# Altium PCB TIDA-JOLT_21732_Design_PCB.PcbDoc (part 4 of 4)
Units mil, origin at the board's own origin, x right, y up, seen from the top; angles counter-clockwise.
Board outline 5511.81 x 3149.61 mil, 4 copper layers (Top Layer, Power, Ground, Bottom Layer), stack 104.204 mil thick; 440 components, 201 nets, 1044 pads, 391 vias.
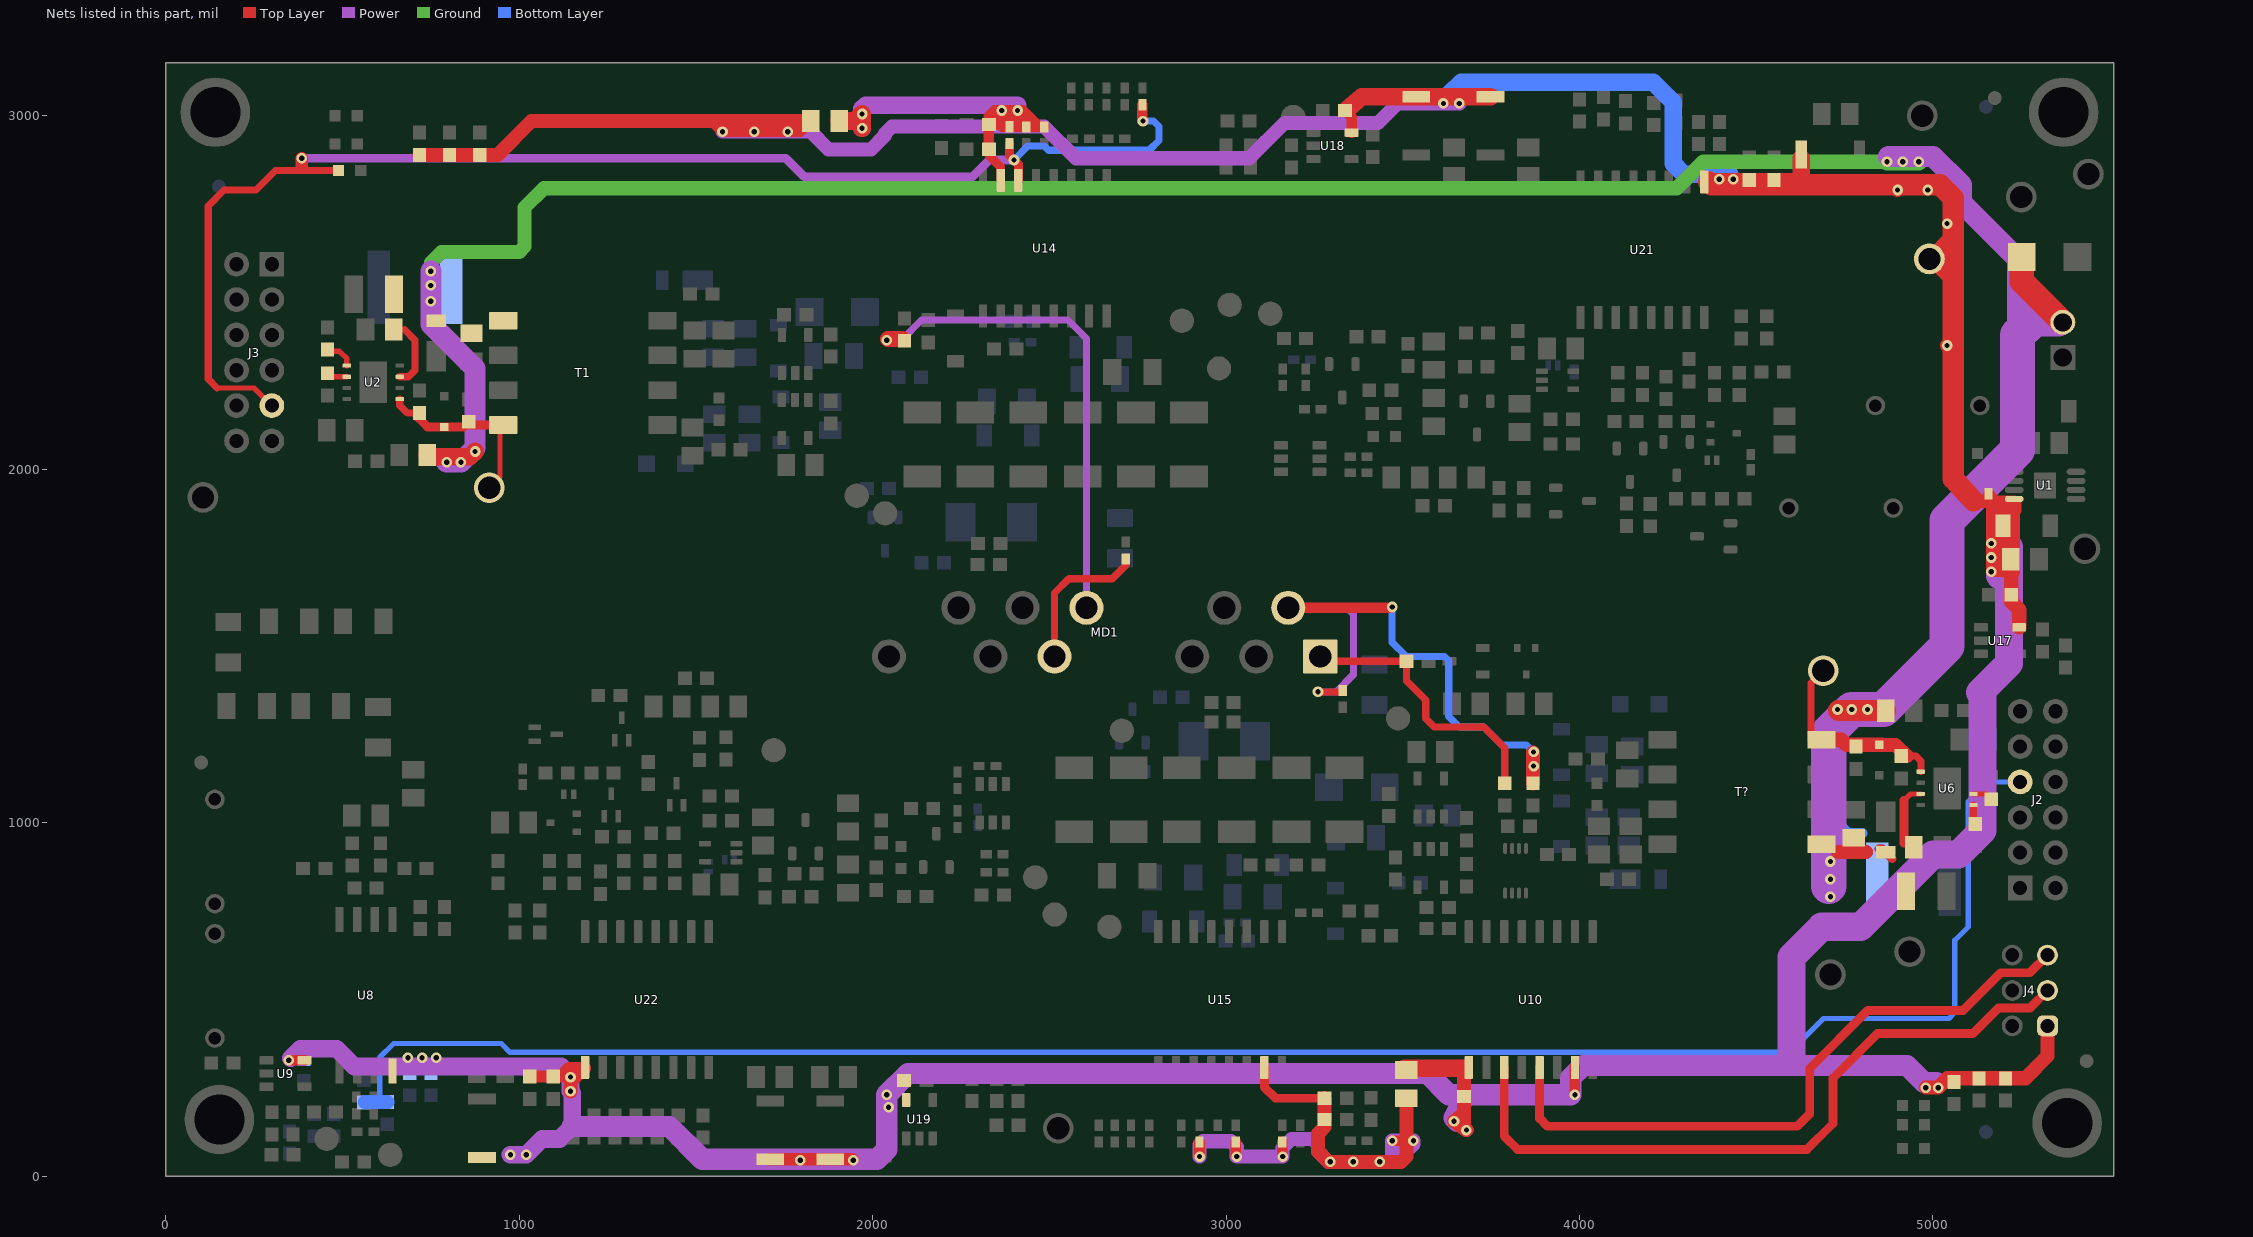
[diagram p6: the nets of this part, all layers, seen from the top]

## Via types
v1: diameter 30, hole 15, Top Layer to Bottom Layer, 378 vias
v2: diameter 19.68, hole 7.87, Top Layer to Bottom Layer, 13 vias

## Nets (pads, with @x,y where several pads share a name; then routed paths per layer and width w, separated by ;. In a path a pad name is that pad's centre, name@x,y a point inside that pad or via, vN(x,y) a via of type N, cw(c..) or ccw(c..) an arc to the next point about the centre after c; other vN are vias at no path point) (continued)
RST/EN_U: C85.1 D22.1 J3.9 R61.1 U14.14 | length 3881
  Top Layer w15: 145,2230 250,2230 J3.9@300,2180
  Top Layer w20: 145,2230 120,2255 120,2745 165,2790 255,2790 310,2845 D22.1@488.5,2845
  Top Layer w25: R61.1@2387.18,2921.73 2387.18,2887.82 v1(2400,2875) 2412.18,2862.82 U14.14@2412.18,2817.28
  Top Layer w30: v1@2763.31,2986.69 C85.1@2763.31,3031.1
  Top Layer w35: 385,2860 v1(385,2880)
  Power w25: v1(385,2880) 1754.11,2880 1806.56,2827.55 2282.55,2827.55 2330,2875 v1(2400,2875)
  Bottom Layer w20: v1(2400,2875) 2440,2915 2485,2915 2497.55,2902.45 2782.45,2902.45 2810,2930 2810,2970 2795,2985 v1(2765,2985)
SCLK_temp_L: J4.3 U10.3 | length 2009.2
  Top Layer w25: U10.3@3787.05,307.44 3787.05,112.95 3825,75 4643.51,75 4717.13,148.62 4717.13,277.13 4842.87,402.87 5112.87,402.87 5185,475 5274.37,475 J4.3@5324.33,524.96
SDO_temp_L: J4.5 U10.5 | length 1866.8
  Top Layer w25: U10.5@3887.05,307.44 3887.05,162.95 3909.25,140.75 4616.28,140.75 4651.38,175.85 4651.38,304.36 4815.64,468.62 5085.64,468.62 5192.02,575 5274.37,575 J4.5@5324.33,624.96
SS_L: C38.1 U6.5 | length 55.3
  Top Layer w20: U6.5@5114.93,1049.6 5114.93,1001.44 C38.1@5120,996.37
SS_U: C17.1 U2.5 | length 83.5
  Top Layer w15: C17.1@457.1,2333.5 491.5,2333.5 512.29,2312.71 U2.5@512.29,2293
SW_L: C26.2 D14.2 R17.2 T?.4 TP3.1 U6.1 | length 595
  Top Layer w20: T?.4@4655,1233.8 4655,1395 TP3.1@4690,1430 ; R17.2@4911.1,1188.35 4951.65,1188.35 4966.3,1173.7 U6.1@4966.3,1144.09
  Top Layer w40: T?.4@4685,1234.44 4740.56,1234.44 4754.84,1220.16 D14.2@4856.1,1220.16 ; 4822.76,1220 4894.45,1220 R17.2@4926.1,1188.35
SW_U: C6.2 D5.2 R6.2 T1.4 TP1.1 U2.1 | length 523.4
  Top Layer w15: TP1.1@915,1947.4 945.4,1977.8 T1.4@945.4,2125.56
  Top Layer w20: U2.1@661.9,2198.52 661.9,2179.84 683.24,2158.5 R6.2@715,2158.5
  Top Layer w25: R6.2@715,2158.5 715,2145 740.7,2119.3 D5.2@788.2,2119.3 842.13,2119.3 C6.2@857.1,2134.26 ; C6.2@855.39,2125 T1.4@935,2125
T_L+: MD1.4 R43.1 R171.1 | length 791.7
  Top Layer w20: MD1.4@3266.38,1470 3279.8,1456.58 R171.1@3510.08,1456.58 3510.08,1401.38 3565,1346.46 3565,1295 3590,1270 3730,1270 3788.5,1211.5 R43.1@3788.5,1111.5
T_L-: MD1.5 R44.1 R82.2 | length 1714.9
  Top Layer w20: v1(3260,1370) 3326.38,1370 R82.2@3330,1373.62
  Top Layer w30: MD1.5@3190,1593.62 MD1.5@3175.83,1607.8 v1@3467.8,1607.8
  Top Layer w40: R44.1@3868.5,1111.5 v1@3868.5,1198.5
  Power w20: MD1.5@3175.83,1607.8 3342.2,1607.8 3360,1590 3360,1418.35 3311.65,1370 v1(3260,1370)
  Bottom Layer w20: v1(3470,1610) 3470,1510 3510,1470 3618.31,1470 3630,1458.31 3630,1300 3660,1270 3730,1270 3780,1220 3850,1220 v1(3870,1200) v1(3870,1160)
T_U+: MD1.9 R72.1 | length 1414.2
  Top Layer w45: v1@2043.5,2368.5 R72.1@2085,2368.5
  Power w20: v1(2040,2365) 2081.18,2365 2138.63,2422.45 2552.47,2422.45 2604.96,2369.96 MD1.9@2604.96,1607.8
T_U-: MD1.10 R78.2 | length 432
  Top Layer w20: MD1.10@2514.41,1470 2514.41,1649.41 2555,1690 2678,1690 2716.26,1728.26 R78.2@2716.26,1746.38
TC_L: R18.1 U6.6 | length 56.3
  Top Layer w15: U6.6@5114.93,1081.1 5150.08,1081.1 R18.1@5165,1066.18
TC_U: R7.1 U2.6 | length 57.3
  Top Layer w15: R7.1@457.1,2266.5 462.08,2261.51 U2.6@512.29,2261.51
V_DCBus: C49.1 J2.7 R36.1 | length 5504.7
  Bottom Layer w15: 598.15,209.53 605,216.38 605,335 645,375 949,375 974,350 4595,350 4690.76,445.76 5045,445.76 5061.85,462.6 5061.85,666.85 5100,705 5100,1059.96 5155,1114.96 J2.7@5246.77,1114.96
  Bottom Layer w40: R36.1@563.39,209.53 598.15,209.53 C49.1@626.69,209.53
VCC1: C4.1 C5.1 C43.1 C44.2 C46.2 C55.2 C100.1 C101.2 C102.2 C108.2 C112.1 C121.2 C125.1 J4.1 R4.2 R58.1 R75.1 R76.1 R77.1 R83.1 R102.1 R103.1 R104.1 S1.1 S2.1 S3.1 S4.1 S5.1 S6.1 TP18.1 U1.8 U8.8 U9.5 U10.1 U10.7 U17.5 U18.5 U19.5 U21.1 U22.1 | length 17364.6
  Top Layer w30: v1(347.4,327.4) U9.5@392.87,327.4 ; 1545,2985 v1(1575,2955) v1(1665,2955) v1(1760,2955) 1795,2955 R58.1@1825,2985 ; C101.2@3336.5,3025.55 C101.2@3336.5,3015 3355.23,2996.26 U18.5@3355.23,2952.4 ; v1@3987.05,235 U10.7@3987.05,307.44 ; R4.2@5157.4,1930.51 5177.88,1910.03 U1.8@5229.8,1910.03 ; 5165,1898.54 v1(5165,1790) v1(5165,1750) v1(5165,1710) 5190,1710 ; 5190,1897.91 5190,1710 ; 5221.18,1710 5190,1710
  Top Layer w35: C125.1@1030,281.5 C121.2@1096.3,281.5 ; 1116.3,281.5 1139.8,305 U22.1@1183,305 ; S4.1@1710,47.32 S6.1@1880,47.32 v1@1942.68,47.32
  Top Layer w40: R75.1@717.95,2889.33 R76.1@802.95,2889.33 R77.1@887.95,2889.33 939.33,2889.33 1035,2985 1545,2985 R58.1@1825,2985 ; v1(1145,240) 1145,267 U22.1@1183,305 ; 3675,305 3673.5,303.5 C55.2@3673.5,225 3673.5,180 ; v1(4900,2790) 4900,2805 ; v1(4980,250) v1(5015,250) 5041.5,276.5 R103.1@5130,276.5 R104.1@5205,276.5 5261.5,276.5 5324.33,339.33 J4.1@5324.33,424.96 ; v1(5040,2350) 5057.63,2350 ; 5040,2550 4995,2595 TP18.1@4990,2595 5057.63,2662.63 ; 5114.97,1910.03 5153.51,1910.03 ; 5220.47,1834.13 5220.47,1875.47 5221.5,1876.5 5230,1885 5230,1900 ; 5221.5,1709.68 C100.1@5221.5,1645 5221.5,1625 5244.13,1602.36 U17.5@5244.13,1552.4 ; 3673.5,180 3648.5,155 v1(3645,155) v1(3680,130) 3673.5,136.5 3673.5,180
  Top Layer w50: C101.2@3345,3020 3383.98,3053.98 ; 3388.98,3053.98 S3.1@3537.91,3053.98 S1.1@3747.91,3053.98 ; R83.1@3505,305.1 3510,305.1 3672.01,305 ; 4365,2813.23 4613.23,2813.23 4627.32,2827.32 S2.1@4627.32,2880 ; 5220.47,1875.47 5220.47,1890.47 ; 5221.5,1709.68 5221.5,1876.5 5221.5,1891.5
  Top Layer w60: 4365,2813.23 4373.23,2805 4900,2805 5020,2805 5057.63,2767.37 5057.63,2662.63 5057.63,2350 5057.63,1972.37 5065,1965 5114.97,1910.03
  Power w40: v1(1575,2955) v1(1665,2955) v1(1760,2955) 1825,2955 1875,2905 1995,2905 2035,2945 2035,2950 2055,2970 2485,2970 2575,2880 3065,2880 3165,2980 3430,2980 3485,3035 v1(3615,3035) v1(3660,3035) ; v1(3645,155) 3655,155 v1(3680,130)
  Power w50: v1@353.55,333.55 379.98,359.98 483.52,359.98 533.5,310 1118.5,310 1145,283.5 v1(1145,280) v1(1145,240) 1150,235 1150,140 1115,105 1065,105 v1(1020,60) v1(975,60)
  Power w60: 1150,140 1425,140 1517.68,47.32 2012.32,47.32 2040,75 v1(2040,230) 2100,290 3570,290 3630,230 3677.5,230 ; v1@3655,155 3645,165 3677.5,230 ; 5010,265 4975,265 4927.02,312.98 4010.53,312.98 3975,277.45 3975,230 3677.5,230 ; 5190,1700 5215,1675
  Power w80: 4600,327.55 4600,620 4685,705 4795,705 5000,910 5072.45,910 5140,977.55 5140,1360.87 5132.93,1367.93 5215,1450 5215,1675 5215,1778.96 5190,1803.96 5190,1700
  Bottom Layer w30: v1(347.4,327.4) v1@348.86,327.4 ; v1(3615,3035) v1(3660,3035)
  Bottom Layer w35: v1@351.5,331.5 C44.2@390,331.5
  Bottom Layer w50: 3635,3050 3635,3065 3665,3095 4208.54,3095 4265,3038.54 4265,2865 4295,2835 4425,2835
  other v1: 1795,45 1945,45 2045,195 3987.05,230 685,335 725,335 765,335 5040,2695 4985,2790 4395,2820 4435,2820
VCC_L: C89.2 C90.1 R83.2 R85.2 R86.2 R87.2 U15.15 | length 1896.1
  Top Layer w25: U15.15@3108.31,307.44 3108.31,251.69 3140,220 3258.5,220 ; 3278.5,138.5 C90.1@3278.5,160
  Top Layer w30: v1@2924.75,55.25 R85.2@2924.75,96.38 ; v1@3027.38,57.62 R86.2@3027.38,96.38 ; R87.2@3158.69,96.38 3158.69,56.31 v1(3160,55) ; v1(3470,100) 3510,100 v1(3530,100)
  Top Layer w40: 3260,120 3260,70 3290,40 v1(3295,40) v1(3360,40) v1(3435,40) 3495,40 3510,55 3510,100 R83.2@3510,220 ; 3265,125 3278.5,138.5 ; C90.1@3278.5,160 C89.2@3278.5,220
  Power w40: v1(2925,55) 2925,88.35 2935,98.35 3014.03,98.35 3030,82.38 v1(3030,55) v1(3160,55) 3160,79.66 3185.34,105 3245,105 3260,90 3260,70 3290,40 v1(3295,40) v1(3360,40) v1(3435,40) 3480,40 3505,65 ; 3505,65 3530,90 v1(3530,100) v1(3470,100) 3470,65 3505,65
VCC_U: C68.2 C71.1 R58.2 R59.2 R60.2 R61.2 U14.15 | length 1212.7
  Top Layer w25: C68.2@2328.68,2905.35 2328.68,2888.13 2362.18,2854.63 U14.15@2362.18,2817.28
  Top Layer w30: C68.2@2328.68,2905.35 C71.1@2328.68,2975.35 ; 2356.38,2988.62 2415,2988.62 R60.2@2435,2968.62 ; 2464.5,2975.5 2425,3015 v1(2410,3015) v1(2365,3015) 2345,3015 2328.68,2998.68 C71.1@2328.68,2975.35 ; R59.2@2485,2968.62 R60.2@2435,2968.62 ; C71.1@2328.68,2975.35 2359.65,2975.35 2366.38,2968.62 R60.2@2435,2968.62
  Top Layer w50: R58.2@1905,2985 1950,2985 v1(1970,3005) v1(1970,2965)
  Power w50: v1(1970,2965) v1(1970,3005) 1970,3020 1980,3030 2395,3030 2410,3030
Vin: C1.1 C2.1 C3.1 C23.1 C24.1 C25.1 D1.2 D2.2 D11.2 J1.2 R1.2 R5.2 R12.2 R16.2 T1.1 T?.1 U2.3 U6.3 | length 9245.6
  Top Layer w15: 4918.56,1062.63 4937.03,1081.1 U6.3@4965.32,1081.1
  Top Layer w20: U2.3@661.9,2261.51 686.51,2261.51 705,2280 705,2365 675,2395
  Top Layer w25: D11.2@4846.82,925 4857.56,925 4885,897.56 ; 4918.56,942.54 4918.56,1062.63 ; C25.1@4933.56,942.54 C25.1@4946.1,930
  Top Layer w40: 4731.1,916.65 4810.91,916.65
  Top Layer w50: R5.2@740,2040 745,2035 860,2035 v1(875,2050)
  Top Layer w60: v1@4733.15,1316.85 R16.2@4866.1,1316.85
  Top Layer w70: D1.2@5251.26,2600 5251.26,2531.73 J1.2@5367.4,2415.59
  Power w60: v1(750,2520) v1(750,2475) 750,2410 875,2285 875,2060 v1(835,2020) v1(795,2020) ; v1@750,2530 v1(750,2560) ; 4875,2885 5000,2885 5080,2805 5080,2755 5239.45,2595.55 5239.45,2379.45
  Power w80: 5275.59,2415.59 J1.2@5355,2415
  Power w100: 4705,820 4705,1255 v1(4770,1320) v1(4815,1320) 4860,1320 5040,1500 5040,1855 5239.45,2054.45 5239.45,2379.45 5275.59,2415.59
  Ground w40: v1(750,2475) v1(750,2520) v1(750,2560) 750,2585 780,2615 1000,2615 1015,2630 1015,2740 1070,2795 4275,2795 4350,2870 v1(4870,2870)
  Ground w50: v1(4870,2870) v1(4915,2870) v1(4960,2870)
  Bottom Layer w30: v1(4730,1320) 4730,1000 4760,970 4800,970
  other v1: 4710,790 4710,840 4710,890
pads on no net: FID1.1 FID2.1 FID3.1 FID4.1 FID5.1 FID6.1 T1.2 T1.3 T?.2 T?.3 U2.9@587.1,2216.04 U2.9@587.1,2275.48 U3.3 U5.3 U6.9@5040.13,1067.12 U6.9@5040.13,1126.57 U22.7

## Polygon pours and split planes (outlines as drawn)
GND on Bottom Layer "Top Layer-No Net 2" (solid, pour order 122): 550,2310.59 540,2300.59 540,2173.03 550,2163.03 620,2163.03 630,2173.03 630,2303.03 622.44,2310.59
ISO_GND_L on Bottom Layer "BOTTOM_LAYER_ISO_GND_L_P116" (solid, pour order 116): 3610.04,1230 3725,1230 3760,1195 3760,1095 3750,1085 3620,1085 3595,1110 3595,1214.96
Vin on Bottom Layer "Top Layer-No Net 2" (solid, pour order 88): 690,2340.83 670,2360.83 670,2610.83 680,2620.83 870,2620.83 900,2590.83 900,2040.83 860,2000.83 750,2000.83 740,2010.83 740,2320 719.17,2340.83 690,2340.83 670,2360.83
-8V_Iso_U on Bottom Layer "Top Layer-No Net 2" (solid, pour order 84): 2780,2432.93 2790,2422.93 2790,2227.93 2750,2187.93 2670,2187.93 2660,2197.93 2660,2412.93 2680,2432.93
+15V_Iso_U on Bottom Layer "Top Layer-No Net 2" (solid, pour order 82): 2565,2065 2605,2105 2605,2390 2510,2390 2485,2365 2485,2270 2460,2245 2420,2245 2405,2230 2405,2090 2430,2065
ISO_GND_L on Bottom Layer "Top Layer-No Net 2" (solid, pour order 78): 3075.4,930.4 3203.14,930.4 3225,908.54 3225,685 3180,640 3051.63,640 3040,651.63 3040,905.4 3065,930.4 3080,930.4
ISO_GND_L on Bottom Layer "Top Layer-No Net 2" (solid, pour order 76): 3455,1310 3455,1365 3445,1375 3340,1375 3308.35,1343.35 3308.35,1320 3293.35,1305 3130,1305 3040,1215 3040,1123.5 3064.25,1099.25 3180.75,1099.25 3260,1030.36 3260,825 3300,785 3495,785 3510,800 3510,880 3485,905 3355,905 3340,920 3340,1150 3390,1200 3390,1270 3429.49,1270 3455.43,1295.94 3455.43,1365
+15V_Iso_L on Bottom Layer "Bottom Layer-No Net" (solid, remove dead copper, pour order 0): 2880,930 3037.4,930 3045,922.4 3045,763.74 3035.83,754.57 2974.57,754.57 2940,720 2940,695 2930,685 2882.6,685 2870,697.6 2870,920
Vin on Bottom Layer "Top Layer-No Net 2" (solid, pour order 14): 4890,990 4910,970 4910,720 4900,710 4710,710 4680,740 4680,1290 4720,1330 4830,1330 4840,1320 4840,1010.83 4860.83,990 4890,990 4910,970
GND on Bottom Layer "Top Layer-No Net 2" (solid, pour order 16): 5015,1183.84 5005,1173.84 5005,1046.28 5015,1036.28 5085,1036.28 5095,1046.28 5095,1176.28 5087.44,1183.84
GND on Bottom Layer "Top Layer-No Net 2" (solid, pour order 20): 4930,740 4950,720 5060,720 5080,740 5080,940 5050,970 4940,970 4930,960
NetC27_1 on Bottom Layer "Top Layer-No Net 2" (solid, pour order 24): 4175,810 4165,800 3940,800 3920,820 3920,950 3935,965 4165,965 4175,955
NetC32_2 on Bottom Layer "Top Layer-No Net 2" (solid, pour order 28): 3955,1190 3920,1225 3920,1320 3955,1355 4135,1355 4155,1335 4155,1265 4180,1240 4180,1200 4170,1190
ISO_GND_L on Bottom Layer "Top Layer-No Net 2" (solid, pour order 32): 4008.98,1155 4015,1161.02 4015,1165 4177.52,1165 4197.52,1145 4245,1145 4250,1140 4250,1020 4245,1015 4180,1015 4170,1005 4170,995 4165,990 3940,990 3925,1005 3925,1145 3935,1155
VCC1 on Bottom Layer "Top Layer-No Net 2" (solid, pour order 54): 630,325 645,340 780,340 790,330 790,285 775,270 640,270 630,280
ISO_GND_U on Bottom Layer "Top Layer-No Net 2" (solid, pour order 94): 1410,2345 1385,2320 1385,2160 1415,2130 1750,2130 1770,2150 1770,2255 1785.13,2270.13 1870.12,2270.13 1890,2290.02 1890,2465 1870,2485 1790,2485 1775,2470 1775,2357.35 1762.65,2345
GND on Bottom Layer "Top Layer-No Net 2" (solid, pour order 110): 810,245 835,220 835,40 815,20 604.98,20 580,44.98 580,146.85 598.15,165 650,165 670,185 670,245 675,250 805,250
ISO_GND_U on Top Layer "Top Layer-ISO_GND_U" (solid, pour order 120): 2470,1600 2470,1695 2495,1720 2495,1815.32 2475.32,1835 2385.87,1835 2355,1804.13 2355,1715.28 2375.28,1695 2375,1615 2395,1595 2460,1595
ISO_GND_L on Top Layer "Top Layer-ISO_GND_L" (solid, pour order 118): 3040,1485 3040,1390 3015,1365 3015,1269.68 3034.68,1250 3125.87,1250 3155.87,1280 3155,1280.87 3155,1369.72 3134.72,1390 3135,1390.28 3135,1470 3115,1490 3050,1490
ISO_GND_L on Top Layer "TOP_LAYER_ISO_GND_L_P114" (solid, pour order 114): 3440,1065.75 3445,1070.75 3445,1220 3458.5,1233.5 3702.24,1233.5 3789.45,1146.3 3789.45,895.67 3767.79,874.02 3460.98,874.02 3438.74,896.26 3438.74,1080 3457.32,1098.58
ISO_GND_U on Top Layer "TOP_LAYER_ISO_GND_U_P112" (solid, pour order 112): 1900,2110 1900,2300 1871.5,2328.5 1646.24,2328.5 1610,2292.26 1610,2120 1630,2100 1885,2097.76
GND on Top Layer "Top Layer-No Net 2" (solid, pour order 100): 554.05,2015 636.1,2097.06 636.1,2576.1 725,2665 1020,2665 1040,2685 1040,2745 1075,2780 5501.62,2780 5501.62,3093.38 5455,3140 15,3140 0,3125 0,2060 45,2015
ISO_GND_U on Top Layer "Top Layer-No Net 2" (solid, pour order 98): 4425,2375 4440,2390 4550,2390 4560,2380 4560,2330 4535,2305 4535,2290 4535,2266 4515,2250 4515,2135 4435,2135 4420,2150 4420,2370
Vin on Top Layer "Top Layer-No Net 2" (solid, pour order 92): 625,2555 660,2590 960,2590 995,2555 995,2440 955,2400 916.97,2400 900,2383.03 900,2365 891.44,2356.44 833.21,2356.44 788.83,2400.83 710.83,2400.83 675,2365 620,2365 620,2550 660,2590
-8V_Iso_U on Top Layer "Top Layer-No Net 2" (solid, pour order 86): 2650,2455 2665,2470 2815,2470 2835,2450 2835,2385 2820,2370 2675,2370 2650,2395
ISO_GND_U on Top Layer "Top Layer-No Net 2" (solid, pour order 80): 2420,2385 2425,2380 2425,2260 2405,2240 2159.45,2240 2139.45,2260 2139.45,2379.45 2145,2385
ISO_GND_U on Top Layer "Top Layer-No Net 2" (solid, pour order 74): 2645,1780 2620,1805 2620,1863.7 2641.3,1885 2780,1885 2795,1870 2795,1795 2780,1780
VCC1 on Top Layer "Top Layer-No Net 2" (solid, pour order 56): 2035,280 2025,270 2025,190 2035,180 2097.44,180 2105,187.56 2105,270 2095,280
+5V_L on Top Layer "Top Layer-No Net 2" (solid, pour order 64): 633.5,690 675,690 680,695 680,815 670,825 650,825 640,815 640,775 630,765 630,693.5
ISO_GND_L on Top Layer "Top Layer-No Net 2" (solid, pour order 62): 1750.02,730 1770,710.02 1770,710 1875,710 1900,735 1900,795 1935,830 2050,830 2062.2,842.2 2100,842.2 2110,832.2 2110,680 2090,660 1735,660 1715,680 1715,715 1740,740
ISO_GND_L on Top Layer "Top Layer-No Net 2" (solid, pour order 60): 1535,725 1560,700 1645,700 1675,730 1675,770 1710.02,770 1760,720.02 1760,675 1745,660 1485,660 1475,670 1475,715 1485,725
ISO_GND_L on Top Layer "Top Layer-No Net 2" (solid, pour order 48): 788.54,898.54 725,898.54 720,893.54 720,840 700,820 700,745 705,740 950,740 960,730 1090,730 1105,745 1105,845 1100,850 855,850 806.46,898.54
NetR94_1 on Top Layer "Top Layer-No Net 2" (solid, pour order 46): 2985,915 2972.91,927.09 2972.91,987.91 2985,1000 3397.99,1000 3410,987.99 3410,925 3400,915
NetR89_1 on Top Layer "Top Layer-No Net 2" (solid, pour order 44): 2505,920 2495,930 2495,995 2505,1005 2922.99,1005 2935,992.99 2935,930 2925,920
Gate_L on Top Layer "Top Layer-No Net 2" (solid, pour order 42): 2481.97,1145 2481.97,1124.06 2491.02,1115 3377.91,1115 3396.97,1134.06 3396.97,1190 3386.97,1200 2491.97,1200 2481.97,1190
+3.3V_L on Top Layer "Top Layer-No Net 2" (solid, pour order 10): 3690,650 3620,650 3600,670 3600,820 3619.11,839.11 3698.09,839.11 3698.98,840 3708.82,830.16 3708.82,658.82 3700,650
ISO_GND_L on Top Layer "Top Layer-No Net 1" (solid, pour order 6): 3270,1340 3265,1335 3265,1241.3 3276.3,1230 3365,1230 3375,1240 3375,1335 3370,1340
-8V_Iso_L on Top Layer "Top Layer-No Net" (solid, pour order 2): 2759.49,795 2750,785.51 2750,674.49 2764.49,660 2814.49,660 2824.49,670 2824.49,785 2814.49,795
Vin on Top Layer "Top Layer-No Net 2" (solid, pour order 12): 4798.82,939.85 4940.71,939.85 4950.56,930 4950.56,747.72 4928.67,725.83 4682.84,725.83 4648.67,760 4648.67,940 4658.67,950 4679.77,950 4709.77,980 4778.67,980 4778.67,960
ISO_GND_L on Top Layer "Top Layer-No Net 2" (solid, pour order 22): 3790,940 3780,950 3718.98,950 3698.98,970 3671.57,970 3661.57,960 3661.57,891.34 3682.91,870 3780,870 3790,880
ISO_GND_L on Top Layer "Top Layer-No Net 2" (solid, pour order 30): 4110,1145 4105,1140 4105,975 4115,965 4175,965 4175,1005 4185,1015 4245,1015 4250,1020 4250,1140 4245,1145 4235,1145
GND on Top Layer "Top Layer-No Net 2" (solid, pour order 40): 4920,755 4940,735 5050,735 5070,755 5070,965 5050,985 4930,985 4920,975
ISO_GND_L on Top Layer "Top Layer-No Net 2" (solid, pour order 50): 4025,730 4055,760 4140,760 4160,740 4160,670 4150,660 4040,660 4025,675
GND on Top Layer "Top Layer-No Net 2" (solid, pour order 34): 420,300 435,315 435,325 440,330 499.25,330 505,324.25 505,265 500,260 440,260 420,280 385,280 385,300
VCC1 on Top Layer "Top Layer-No Net 2" (solid, pour order 52): 870,100 1025,100 1035,90 1035,45 1025,35 865,35 855,45 855,90 865,100
VCC1 on Top Layer "Top Layer-No Net 2" (solid, pour order 58): 631.2,325 646.2,340 781.2,340 791.2,330 791.2,285 776.2,270 641.2,270 631.2,280
GND on Top Layer "Top Layer-No Net 2" (solid, remove dead copper, pour order 66): 55,340 4565,340 4810,585 4840,585 4865,610 4865,1400 4935,1470 4980,1470 5030,1520 5030,2750 5000,2780 5000,3145 5005,3150 5005.39,3149.61 5510,3149.61 5510,0 5,0 5,290
Gate_U on Top Layer "Top Layer-No Net 2" (solid, pour order 68): 2992.5,1985 2992.5,2005.94 2983.44,2015 2096.56,2015 2077.5,1995.94 2077.5,1940 2087.5,1930 2982.5,1930 2992.5,1940
NetR63_1 on Top Layer "Top Layer-No Net 2" (solid, pour order 70): 2970,2204.6 2980,2194.6 2980,2129.6 2970,2119.6 2552.01,2119.6 2540,2131.61 2540,2194.6 2550,2204.6
NetR67_1 on Top Layer "Top Layer-No Net 2" (solid, pour order 72): 2492.5,2204.6 2504.59,2192.51 2504.59,2131.69 2492.5,2119.6 2079.51,2119.6 2067.5,2131.61 2067.5,2194.6 2077.5,2204.6
ISO_GND_U on Top Layer "Top Layer-No Net 2" (solid, pour order 96): 1485.1,2337.39 1525.1,2297.39 1525.1,2145.17 1500.53,2120.59 1500.17,2110 1430.22,2110 1420.1,2120.59 1420.1,2197.39 1410.1,2207.39 1372.61,2207.39 1360.99,2219.01 1360.99,2327.46 1370.92,2337.39
ISO_GND_U on Ground "Top Layer-No Net 2" (solid, pour order 108): 1545,2445 1560,2460 4570,2460 4620,2410 4620,1785 4565,1730 4315,1730 4240,1805 3730,1805 3605,1930 2875,1930 2800,1855 2010,1855 1920,1945 1395,1945 1345,1995 1345,2410 1380,2445
ISO_GND_L on Ground "Top Layer-No Net 2" (solid, pour order 106): 2655,1230 2655,1225 2225,1225 2100,1100 1770,1100 1710,1160 1710,1345 1625,1430 1000,1430 925,1355 925,1210 800,1085 430,1085 395,1050 395,730.36 460.36,665 4215,665 4260,710 4260,1345 4220,1385 3409.57,1385 3319.57,1295 2720,1295
GND on Ground "Top Layer-No Net 2" (solid, pour order 104): 660,2010 705,2055 705,2640 725,2660 1020,2660 1040,2680 1040,2740 1075,2775 5501.62,2775 5501.62,3088.38 5455,3135 15,3135 0,3120 0,2055 45,2010
GND on Ground "Top Layer-No Net 2" (solid, remove dead copper, pour order 102): 55,335 4565,335 4810,580 4840,580 4865,605 4865,1395 4935,1465 4980,1465 5030,1515 5030,2745 5000,2775 5000,3140 5005,3145 5005.39,3144.61 5510,3144.61 5510,-5 5,-5 5,285

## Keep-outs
Keep-Out Layer:
  text ".Layer_Name" at 577,-858.49 h60

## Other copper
Top Layer:
  text ".Layer_Name" at 577,-858.49 h60
Power:
  text ".Layer_Name" at 577,-858.49 h60
Ground:
  text ".Layer_Name" at 577,-858.49 h60
Bottom Layer:
  text ".Layer_Name" at 577,-858.49 h60

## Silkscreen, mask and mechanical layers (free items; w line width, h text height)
Top Overlay:
  lines w30: 220,1960 822.19,1960 ; 270,675 445,675 ; 675,335 825,335 ; 700,1610 1230,1610 1360,1610 1360,2055 ; 945,2520 945,2760 945,2795 ; 955,2805 975,2805 2275,2800 ; 1020,335 1150,335 ; 1105,675 1155,675 ; 1575,340 2775,340 ; 1575,675 2610,675 ; 1614.28,2450.59 1694.28,2450.59 ; 1870,2450 2020,2450 ; 2695,2800 3580,2800 ; 2705,2461.15 2825,2461.15 ; 2720,675 2775,675 ; 3190,675 3345,675 ; 3200,340 3440,340 ; 3200,2460 3970,2460 ; 3575,340 3650,340 ; 3705,2800 3790,2800 ; 3925,2800 3970,2800 ; 4080,340 4700,340 4707.02,347.02 4707.02,409.74 ; 4120,675 4230,675 4230,850 ; 4180,1355 4180,1740 4285,1740 ; 4385,2460 4410,2460 ; 4400,2770 4960,2770 4970,2760 4970,2680 ; 4410,1740 4580,1740 4580,1845 ; 4580,1930 4580,2015 ; 4580,2320 4580,2395 ; 4710,680 4710,834.96 ; 4776.1,1480 4960,1480 4970,1490 4970,2050 ; 4970,2305 4970,2505
  text "0V_Inj" at 3435,3105 h30
  text "OI_Inj" at 3655,3095 h30
  text "GND" at 4890,3095 h30
  text "Analog_U" at 2930,3050 h30
  text "5V_Inj" at 4470,2970 h30
  text "INU_ / APWM_U" at 375,2755 h40 r270
  text "INU+" at 5060,2745 h30
  text "Conn_U" at 90,2710 h30
  text "INU-" at 5365,2710 h30
  text "CLMPE" at 2945,2530 h30
  text "VEE2_U" at 2745,2500 h30
  text "VDD2_U" at 3100,2500 h30
  text "12V" at 5290,2495 h30
  text "Vcc1" at 5020,2485 h30
  text "GND  Vin" at 5200,2240 h30 r90
  text "OUTL" at 2995,2200 h30
  text "SW_U" at 1000,1900 h30
  text "GND" at 210,1885 h30
  text "OUT_H" at 1820,1835 h30
  text "Gate_U" at 1975,1775 h30
  text "GND" at 5395,1660 h30
  text "High Voltage" at 1465,1565 h50
  text "OUTH" at 3440,1355 h30
  text "Gate_L" at 2485,1300 h30
  text "VDD2_L" at 1785,1225 h30
  text "OUTL" at 2460,925 h30 r90
  text "VEE2_L" at 2370,615 h30
  text "CLMPE" at 2585,615 h30
  text "INL-" at 4880,505 h30
  text "INL+" at 4665,445 h30
  text "Conn_L" at 5125,435 h30 r90
  text "5VInj" at 690,125 h30
  text "0Vinj" at 1980,40 h30 r90
  text "OI_inj" at 1610,35 h30 r90
  text "BUS_N" at 110,20 h30
  text "BUS_P" at 690,20 h30
  text "Analog_L" at 2410,20 h30
  text ".Layer_Name" at 577,-858.49 h60
Bottom Overlay:
  text ".Layer_Name" at 577,-858.49 h60
Top Paste:
  text ".Layer_Name" at 577,-858.49 h60
Bottom Paste:
  text ".Layer_Name" at 577,-858.49 h60
Top Solder:
  text ".Layer_Name" at 577,-858.49 h60
  text ".Layer_Name" at 577,-858.49 h60
Bottom Solder:
  text ".Layer_Name" at 577,-858.49 h60
Drill Guide:
  text ".Layer_Name" at 577,-858.49 h60
M1 Board Outline:
  the board outline again, w30
  text ".Layer_Name" at 577,-858.49 h60
M2 Board Dimensions:
  rectangle: 125,-400 500,-275
  rectangle: 0,-275 125,-150
  lines w7: 0,-275 1000,-275 ; 125,-400 125,-150 ; 250,-400 250,-150 ; 500,-400 500,-150 ; 750,-400 750,-150 ; 0,-400 0,-150 1000,-150 1000,-400 0,-400
  text ".Layer_Name" at 577,-858.49 h60
M3 3D STEP Top:
  text ".Layer_Name" at 577,-858.49 h60
M4 3D STEP Bottom:
  text ".Layer_Name" at 577,-858.49 h60
M5 Assembly Top:
  lines w10: -292,-930.17 6308,-930.17 ; -292,-726.83 6310,-726.83 ; -292,-523.5 -292,-1133.5 3713,-1133.5 6310,-1133.5 6310,-523.5 -291.5,-523.5 -291.5,-1133.5 1284,-1133.5 ; 2173,-1133.5 2173,-523.5 ; 3440,-726.83 3440,-523.5 ; 4280,-726.83 4280,-523.5 ; 4902,-1140 4902,-937.17
  text "COMPONENTS MARKED 'DNP' SHOULD NOT BE POPULATED." at 1153.5,-318.5 h60
  text "ASSEMBLY VARIANT:" at 1153,-434 h60
  text ".VariantName" at 2189,-434 h60
  text "PCB VIEWED FROM TOP SIDE" at -228.5,-655.67 h60
  text "BOARD #:" at 2248,-655.67 h60
  text ".PRJ_Number" at 2793.5,-655.67 h60
  text "REV:" at 3638,-655.67 h60
  text ".PCB_Rev" at 3929.5,-655.67 h60
  text "SVN REV:" at 4476,-655.67 h60
  text ".VersionControl_RevNumber" at 4982,-655.67 h60
  text "TID #:" at 2248,-859 h60
  text ".TID" at 2793.5,-859 h60
  text "PLOT NAME =" at -228.5,-1064.34 h60
  text ".plot_File_Name" at 577,-1064.34 h60
  text "GENERATED    :" at 2250,-1064.34 h60
  text ".Print_Date" at 3119.5,-1064.34 h60
  text ".Print_Time" at 3848.5,-1064.34 h60
  text "TEXAS INSTRUMENTS" at 5113,-1064.34 h60
M6 Assembly Bottom:
  lines w10: -292.5,-727.33 6309.5,-727.33 ; -290.5,-930.67 6309.5,-930.67 ; 1115.5,-1140.5 1115.5,-937.67 ; 1737.5,-727.33 1737.5,-524 ; 2577.5,-727.33 2577.5,-524 ; 3844.5,-1134 3844.5,-524 ; 4733.5,-1134 6309,-1134 6309,-524 -292.5,-524 -292.5,-1134 2304.5,-1134 6309.5,-1134 6309.5,-524
  text "COMPONENTS MARKED 'DNP' SHOULD NOT BE POPULATED." at 6102,-318 h60
  text ".VariantName" at 5058,-434 h60
  text "ASSEMBLY VARIANT:" at 6097,-434 h60
  text ".VersionControl_RevNumber" at 1035.5,-656.17 h60
  text "SVN REV:" at 1541.5,-656.17 h60
  text ".PCB_Rev" at 2088,-656.17 h60
  text "REV:" at 2379.5,-656.17 h60
  text ".PRJ_Number" at 3224,-656.17 h60
  text "BOARD #:" at 3769.5,-656.17 h60
  text "PCB VIEWED FROM BOTTOM SIDE" at 6246,-656.17 h60
  text ".TID" at 3224,-859.5 h60
  text "TID #:" at 3769.5,-859.5 h60
  text "TEXAS INSTRUMENTS" at 904.5,-1064.84 h60
  text ".Print_Time" at 2169,-1064.84 h60
  text ".Print_Date" at 2898,-1064.84 h60
  text "GENERATED    :" at 3767.5,-1064.84 h60
  text ".plot_File_Name" at 5440.5,-1064.84 h60
  text "PLOT NAME =" at 6246,-1064.84 h60
M9 Title Sheet:
  drawing of 57 lines, arcs and shapes, not listed
  text "1" at 739.84,8036.5 h70
  text "2" at 3235.5,8036.5 h70
  text "3" at 5724.84,8036.5 h70
  text "4" at 8231.51,8036.5 h70
  text "5" at 10730.5,8036.5 h70
  text "6" at 13235.5,8036.5 h70
  text "A" at -416.5,6893.5 h70
  text "A" at 14383.5,6893.5 h70
  text "B" at -416.5,4513.5 h70
  text "B" at 14383.5,4513.5 h70
  text "C" at -416.5,2138.5 h70
  text "C" at 14383.5,2138.5 h70
  text "PROJECT TITLE:" at 11343.5,277.5 h45
  text "SiC isolated gate driver reference" at 11885,230 h70
  text "design with thermal diode and sensing FET" at 11435,115 h70
  text "DESIGNED FOR:" at 11343.5,-23.5 h45
  text ".PRJ_Customer" at 11393.5,-163.5 h70
  text "D" at -416.5,-231.5 h70
  text "D" at 14383.5,-231.5 h70
  text "FILE NAME:" at 11343.5,-323.5 h45
  text ".PCB_File_Name_No_Path" at 11393.5,-443.5 h70
  text "Texas Instruments (TI) and/or its licensors do not warrant the accuracy or completeness of this specification" at 6374,-605.34 h45
  text "ENGINEER:" at 11343.5,-613.5 h45
  text "LAYOUT BY:" at 12848.5,-613.5 h45
  text "or any information contained therein. TI and/or its licensors do not warrant that this design will meet" at 6329.01,-718 h45
  text ".PRJ_Engineer" at 11393.5,-768.49 h70
  text ".PCB_Layout" at 12899,-768.49 h70
  text "the specifications, will be suitable for your application or fit for any particular purpose, or will operate in" at 6329.01,-830.67 h45
  text ".Layer_Name" at 577,-858.49 h60
  text "ALTIUM DESIGNER VERSION:" at 12848.5,-923.5 h45
  text "an implementation. TI and/or its licensors do not warrant that the design is production worthy. You should" at 6329.01,-943.33 h45
  text "completely validate and test your design implementation to confirm the system functionality for your application." at 6374,-1056 h45
  text ".print_Scale" at 11393.5,-1056.83 h70
  text ".Application_BuildNumber" at 12899,-1056.83 h70
  text "1" at 739.84,-1263.5 h70
  text "2" at 3235.5,-1263.5 h70
  text "3" at 5724.84,-1263.5 h70
  text "4" at 8231.51,-1263.5 h70
  text "5" at 10730.5,-1263.5 h70
  text "6" at 13235.5,-1263.5 h70
M10 Fab Notes:
  drawing of 189 lines, arcs and shapes, not listed
  text "DESIGN INFORMATION" at 12382.02,6356.17 h60
  text "MIN. TRACK WIDTH:" at 11737.46,6224.05 h60
  text "8" at 12833.7,6224.05 h60
  text "MIL" at 12988.46,6224.05 h60
  text "MIN. CLEARANCE:" at 11737.46,6099.92 h60
  text "0.2" at 12773.7,6099.93 h60
  text "mm" at 12988.46,6099.92 h60
  text "MIN. VIA PAD SIZE:" at 11737.46,5975.8 h60
  text "24" at 12803.71,5975.8 h60
  text "MIL" at 12988.46,5975.8 h60
  text "0.05mm (2MIL)" at 12432.46,5845.9 h60
  text "MINIMUM ANNULAR RING" at 11408.23,5837.67 h60
  text "EXTERNAL" at 13140.46,5837.67 h60
  text "PER" at 11608.23,5727.55 h60
  text "IPC-D-275 CLASS 2 LEVEL C" at 11828.23,5727.54 h60
  text "MIL, HOLES" at 13316.46,5627.07 h60
  text "+/-" at 12924,5618.48 h60
  text "+/-" at 13778,5618.48 h60
  text "REGISTRATION TOLERANCES:" at 11408.23,5617.42 h60
  text "METAL" at 12608,5617.42 h60
  text "5" at 13184.2,5617.42 h60
  text "3" at 14017.2,5617.42 h60
  text "MIL" at 14133.46,5617.42 h60
  text "HOLE SIZE TOLERANCE (UNLESS OTHERWISE SPECIFIED):" at 11408.23,5519.1 h60
  text "+/-" at 13778,5516.23 h60
  text "3" at 14017.2,5515.17 h60
  text "MIL" at 14133.46,5515.17 h60
  text "MATERIAL:" at 11333.46,5377.52 h60
  text "FR-4 High Tg" at 12319.9,5249 h60
  text "X" at 12175.46,5241.01 h60
  text "FR-408" at 11754.46,5236.49 h60
  text "OTHER" at 13242.46,5236.49 h60
  text "62 MIL (1.6mm) +/-10%" at 12074.56,5093.46 h60
  text "X" at 11954.46,5091.01 h60
  text "THICKNESS:" at 11408.23,5085.24 h60
  text "OTHER" at 13359.46,5085.24 h60
  text "TOLERANCE:" at 11408.23,4946.92 h60
  text "X" at 12256.46,4946.92 h60
  text "ANSI IPC-6012 TYPE 3 CLASS 2" at 12434.48,4946.92 h60
  text "OTHER +/-" at 12434.46,4802.73 h60
  text "BOW & TWIST:" at 11408.23,4657.54 h60
  text "X" at 12256.46,4657.54 h60
  text "ANSI IPC-6012 TYPE 3 CLASS 2" at 12434.48,4657.54 h60
  text "OTHER +/-" at 12434.46,4510.85 h60
  text "DRILLING:" at 11333.46,4380.23 h60
  text "NC_DRILL FILES" at 13094.46,4275.04 h60
  text "REFERENCE:" at 11408.23,4271.1 h60
  text "X" at 12065.46,4271.01 h60
  text "AS SHOWN" at 12243.46,4271.1 h60
  text "X" at 12966.46,4271.1 h60
  text "OTHER" at 13392.46,4128.85 h60
  text "PTH COPPER THICKNESS:" at 11407.91,4125.32 h60
  text "X" at 12547.14,4125.32 h60
  text "20-30 um" at 12675.14,4125.32 h60
  text "BOARD FINISH:" at 11333.46,3977.73 h60
  text "SILKSCREEN:" at 11488.68,3867.6 h60
  text "X" at 12446.46,3867.6 h60
  text "TOP" at 12563.46,3867.6 h60
  text "X" at 12956.46,3867.6 h60
  text "BOTTOM" at 13074.46,3867.6 h60
  text "SILKSCREEN COLOR:" at 11488.68,3712.41 h60
  text "X" at 12445.46,3712.41 h60
  text "WHITE" at 12563.46,3712.41 h60
  text "OTHER" at 13074.46,3712.41 h60
  text "X" at 12576.46,3568.96 h60
  text "GREEN" at 12694.46,3568.96 h60
  text "OTHER" at 13312.46,3568.96 h60
  text "SOLDER RESIST COLOR:" at 11488.68,3562.1 h60
  text "X" at 12576.46,3414.71 h60
  text "MATTE" at 12694.46,3414.71 h60
  text "SEMI-GLOSS" at 13312,3414.07 h60
  text "IMMERSION GOLD (ENIG)" at 12394.46,3241.94 h60
  text "ENEPIG" at 13732,3234.72 h60
  text "SURFACE FINISH:" at 11333.46,3233.72 h60
  text "X" at 12216.46,3233.72 h60
  text "IMM. TIN/SILVER OR EQUIV" at 11663,3096.4 h60
  text "OTHER" at 13094.46,3092.47 h60
  text "ARRAY/PANEL:" at 11333.46,2937.09 h60
  text "CUT AND TRIM PER M1 BOARD OUTLINE" at 12394.46,2928.87 h60
  text "N.C. ROUTE" at 12394.46,2792.9 h60
  text "X" at 13082.46,2792.9 h60
  text "V. SCORE" at 13260.46,2792.9 h60
  text "CERTIFICATION:" at 11333.46,2663.77 h60
  text "MATERIALS AND WORKMANSHIP FOR ALL PCBS" at 12058.46,2663.77 h60
  text "TO MEET OR EXCEED THE REQUIREMENTS OF:" at 12058.46,2569.71 h60
  text "X" at 11695.97,2441.08 h60
  text "ANSI IPC-A-600F CLASS ->" at 11823.96,2441.08 h60
  text "X" at 13471.97,2441.08 h60
  text "2" at 13581.96,2441.08 h60
  text "1" at 13266.96,2439.58 h60
  text "3" at 13935.96,2439.58 h60
  text "X" at 12507.97,2293.39 h60
  text "RoHS" at 12635.96,2293.39 h60
  text "OTHER" at 13280.36,2293.39 h60
  text "PER ORDER" at 13677.42,2293.39 h60
  text "ALL BOARDS MUST MEET OR EXCEED UL94-V0 REQUIREMENTS." at 11361,2139.57 h60
  text "PCB MUST BEAR THE UL94V-0 UL REGISTERED MATERIAL ID NUMBER" at 11361,2023.5 h60
  text "ADDITIONAL REQUIREMENTS:" at 11333.46,1854.08 h60
  text "MICROSECTION:" at 11408.23,1746.95 h60
  text "YES" at 12313.96,1746.95 h60
  text "REQUIRED" at 13175.46,1602.62 h60
  text "BARE BOARD ELEC. TEST:" at 11408.23,1599.76 h60
  text "NONE" at 12713.96,1599.76 h60
  text "X" at 13057.46,1599.76 h60
  text "PER ORDER" at 13767.46,1599.76 h60
  text "XX MIL VIAS REQUIRE NON-CONDUCTIVE FILL AND PLANARIZE" at 11576.38,1394.82 h59
  text "XX MIL VIAS REQUIRE CONDUCTIVE FILL AND PLANARIZE" at 11584.38,1290.84 h60
  text "OUTER XX MIL TRACES REQUIRE 50 OHM SINGLE-ENDED IMPEDANCE" at 11583.39,1127.46 h58
  text "LAYER 2 & 3 (INNER LAYERS) XX MIL WIDE, XX MIL SPACE / TRACES REQUIRE 100 OHM DIFFERENTIAL IMPEDANCE" at 11575.39,891.74 h60
  text ".Layer_Name" at 577,-858.49 h60
M11 Gerber Information:
  lines w10: -292,-930.17 6308,-930.17 ; -292,-726.83 6310,-726.83 ; -292,-523.5 -292,-1133.5 3713,-1133.5 6310,-1133.5 6310,-523.5 -291.5,-523.5 -291.5,-1133.5 1284,-1133.5 ; 2173,-1133.5 2173,-523.5 ; 3440,-726.83 3440,-523.5 ; 4280,-726.83 4280,-523.5 ; 4902,-1140 4902,-937.17
  text "ALL ARTWORK VIEWED FROM TOP SIDE" at -228.5,-655.67 h60
  text "BOARD #:" at 2248,-655.67 h60
  text ".PRJ_Number" at 2793.5,-655.67 h60
  text "REV:" at 3638,-655.67 h60
  text ".PCB_Rev" at 3929.5,-655.67 h60
  text "SVN REV:" at 4476,-655.67 h60
  text ".VersionControl_RevNumber" at 4982,-655.67 h60
  text "LAYER NAME =" at -228.5,-858.49 h60
  text "TID #:" at 2248,-859 h60
  text ".TID" at 2793.5,-859 h60
  text "PLOT NAME =" at -228.5,-1064.34 h60
  text ".plot_File_Name" at 577,-1064.34 h60
  text "GENERATED    :" at 2250,-1064.34 h60
  text ".Print_Date" at 3119.5,-1064.34 h60
  text ".Print_Time" at 3848.5,-1064.34 h60
  text "TEXAS INSTRUMENTS" at 5113,-1064.34 h60
M12 Stackup:
  drawing of 295 lines, arcs and shapes, not listed
  text "Layer" at 9797.84,7740 h60
  text "Name" at 10207.76,7740 h60
  text "Material" at 11137.5,7740 h60
  text "Thickness" at 11997.27,7740 h60
  text "Constant" at 12647.1,7740 h60
  text "Board Layer Stack" at 13216.96,7740 h60
  text "1" at 9797.84,7620 h60
  text "Top Overlay" at 10207.76,7620 h60
  text "2" at 9797.84,7500 h60
  text "Top Solder" at 10207.76,7500 h60
  text "Solder Resist" at 11137.5,7500 h60
  text "0.40mil" at 11997.27,7500 h60
  text "3.5" at 12647.1,7500 h60
  text "3" at 9797.84,7380 h60
  text "Top Layer" at 10207.76,7380 h60
  text "Copper" at 11137.5,7380 h60
  text "1.40mil" at 11997.27,7380 h60
  text "4" at 9797.84,7260 h60
  text "Dielectric 2" at 10207.76,7260 h60
  text "FR-4" at 11137.5,7260 h60
  text "19.69mil" at 11997.27,7260 h60
  text "4.2" at 12647.1,7260 h60
  text "5" at 9797.84,7140 h60
  text "Power" at 10207.76,7140 h60
  text "Copper" at 11137.5,7140 h60
  text "1.42mil" at 11997.27,7140 h60
  text "6" at 9797.84,7020 h60
  text "Dielectric1" at 10207.76,7020 h60
  text "FR-4" at 11137.5,7020 h60
  text "59.20mil" at 11997.27,7020 h60
  text "4.8" at 12647.1,7020 h60
  text "7" at 9797.84,6900 h60
  text "Ground" at 10207.76,6900 h60
  text "Copper" at 11137.5,6900 h60
  text "1.42mil" at 11997.27,6900 h60
  text "8" at 9797.84,6780 h60
  text "Dielectric 3" at 10207.76,6780 h60
  text "FR-4" at 11137.5,6780 h60
  text "19.69mil" at 11997.27,6780 h60
  text "4.2" at 12647.1,6780 h60
  text "9" at 9797.84,6660 h60
  text "Bottom Layer" at 10207.76,6660 h60
  text "Copper" at 11137.5,6660 h60
  text "1.40mil" at 11997.27,6660 h60
  text "10" at 9797.84,6540 h60
  text "Bottom Solder" at 10207.76,6540 h60
  text "Solder Resist" at 11137.5,6540 h60
  text "0.40mil" at 11997.27,6540 h60
  text "3.5" at 12647.1,6540 h60
  text "11" at 9797.84,6420 h60
  text "Bottom Overlay" at 10207.76,6420 h60
  text ".Layer_Name" at 577,-858.49 h60
M13 Component Bodies Top:
  text ".Layer_Name" at 577,-858.49 h60
M14 Component Bodies Bottom:
  text ".Layer_Name" at 577,-858.49 h60
M15 Courtyards Top:
  text ".Layer_Name" at 577,-858.49 h60
M16 Courtyards Bottom:
  text ".Layer_Name" at 577,-858.49 h60
Drill Drawing:
  circle w10: c6293.12,1989.75 r27.63
  lines w10: 6265.5,2141.69 6320.75,2141.69 6293.12,2086.44 6265.5,2141.69 ; 6265.5,2210.76 6293.12,2224.57 6320.75,2210.76 6306.94,2238.39 6320.75,2266.01 6293.12,2252.2 6265.5,2266.01 6279.31,2238.39 6265.5,2210.76 ; 6265.5,2335.08 6320.75,2335.08 6320.75,2390.33 6265.5,2390.33 6265.5,2335.08 ; 6265.5,2473.21 6279.31,2473.21 6279.31,2459.4 6306.94,2459.4 6306.94,2473.21 6320.75,2473.21 6320.75,2500.84 6306.94,2500.84 6306.94,2514.65 6279.31,2514.65 6279.31,2500.84 6265.5,2500.84 6265.5,2473.21 ; 6265.5,2583.72 6265.5,2597.53 6279.31,2611.35 6265.5,2625.16 6265.5,2638.97 6279.31,2638.97 6293.12,2625.16 6306.94,2638.97 6320.75,2638.97 6320.75,2625.16 6306.94,2611.35 6320.75,2597.53 6320.75,2583.72 6306.94,2583.72 6293.12,2597.53 6279.31,2583.72 6265.5,2583.72 ; 6265.5,2721.85 6279.31,2721.85 6293.12,2708.04 6306.94,2721.85 6320.75,2721.85 6306.94,2735.67 6320.75,2749.48 6306.94,2749.48 6293.12,2763.29 6279.31,2749.48 6265.5,2749.48 6279.31,2735.67 6265.5,2721.85 ; 6265.5,2832.36 6320.75,2832.36 6320.75,2887.61 6265.5,2887.61 6265.5,2832.36 ; 6265.5,2984.31 6293.12,2956.68 6320.75,2984.31 6293.12,3011.93 6265.5,2984.31 ; 6276.55,2843.41 6309.7,2843.41 6309.7,2876.56 6276.55,2876.56 6276.55,2843.41
  lines w12: 6215.41,1924.82 9446.9,1924.82 ; 6215.41,3043.7 9446.9,3043.7 ; 6553.27,1800.5 6553.27,3168.02 ; 6885.27,1800.5 6885.27,3168.02 ; 7521.83,1800.5 7521.83,3168.02 ; 7780.97,1800.5 7780.97,3168.02 ; 8156.13,1800.5 8156.13,3168.02 ; 8880.46,1800.5 8880.46,3168.02 ; 6215.41,1800.5 9446.9,1800.5 9446.9,3168.02 6215.41,3168.02 6215.41,1800.5
  text "Symbol" at 6290,3081 h72
  text "Quantity" at 6590.57,3081 h72
  text "Finished Hole Size" at 6922.57,3081 h72
  text "Plated" at 7559.13,3081 h72
  text "Hole Type" at 7818.27,3081 h72
  text "Drill Layer Pair" at 8193.43,3081 h72
  text "Hole Tolerance" at 8917.76,3081 h72
  text "13" at 6590.57,2956.68 h60
  text "7.87mil (0.200mm)" at 6922.57,2956.68 h60
  text "PTH" at 7559.13,2956.68 h60
  text "Round" at 7818.27,2956.68 h60
  text "Top Layer - Bottom Layer" at 8193.43,2956.68 h60
  text "379" at 6590.57,2832.36 h60
  text "15.00mil (0.381mm)" at 6922.57,2832.36 h60
  text "PTH" at 7559.13,2832.36 h60
  text "Round" at 7818.27,2832.36 h60
  text "Top Layer - Bottom Layer" at 8193.43,2832.36 h60
  text "8" at 6590.57,2708.04 h60
  text "35.43mil (0.900mm)" at 6922.57,2708.04 h60
  text "PTH" at 7559.13,2708.04 h60
  text "Round" at 7818.27,2708.04 h60
  text "Top Layer - Bottom Layer" at 8193.43,2708.04 h60
  text "6" at 6590.57,2583.72 h60
  text "39.37mil (1.000mm)" at 6922.57,2583.72 h60
  text "PTH" at 7559.13,2583.72 h60
  text "Round" at 7818.27,2583.72 h60
  text "Top Layer - Bottom Layer" at 8193.43,2583.72 h60
  text "24" at 6590.57,2459.4 h60
  text "40.00mil (1.016mm)" at 6922.57,2459.4 h60
  text "PTH" at 7559.13,2459.4 h60
  text "Round" at 7818.27,2459.4 h60
  text "Top Layer - Bottom Layer" at 8193.43,2459.4 h60
  text "2" at 6590.57,2335.08 h60
  text "51.18mil (1.300mm)" at 6922.57,2335.08 h60
  text "PTH" at 7559.13,2335.08 h60
  text "Round" at 7818.27,2335.08 h60
  text "Top Layer - Bottom Layer" at 8193.43,2335.08 h60
  text "11" at 6590.57,2210.76 h60
  text "62.99mil (1.600mm)" at 6922.57,2210.76 h60
  text "PTH" at 7559.13,2210.76 h60
  text "Round" at 7818.27,2210.76 h60
  text "Top Layer - Bottom Layer" at 8193.43,2210.76 h60
  text "11" at 6590.57,2086.44 h60
  text "63.00mil (1.600mm)" at 6922.57,2086.44 h60
  text "PTH" at 7559.13,2086.44 h60
  text "Round" at 7818.27,2086.44 h60
  text "Top Layer - Bottom Layer" at 8193.43,2086.44 h60
  text "4" at 6590.57,1962.12 h60
  text "141.73mil (3.600mm)" at 6922.57,1962.12 h60
  text "PTH" at 7559.13,1962.12 h60
  text "Round" at 7818.27,1962.12 h60
  text "Top Layer - Bottom Layer" at 8193.43,1962.12 h60
  text "458 Total" at 6590.57,1837.8 h60
  text ".Layer_Name" at 577,-858.49 h60
M17 Embedded Cavity:
  text ".Layer_Name" at 577,-858.49 h60
M18 Embedded Assembly:
  text ".Layer_Name" at 577,-858.49 h60
M19 Embedded Keepout:
  text ".Layer_Name" at 577,-858.49 h60

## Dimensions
0,0 to 0,3149.61 on M2 Board Dimensions
0,0 to 5511.81,0 on M2 Board Dimensions
0,-400 to 1000,-400 on M2 Board Dimensions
